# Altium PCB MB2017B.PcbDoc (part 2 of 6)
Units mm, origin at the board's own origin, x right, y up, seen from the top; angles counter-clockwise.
Board outline 148.19 x 169.19 mm, 4 copper layers (Top Layer, Mid Layer 1, Mid Layer 2, Bottom Layer), stack 1.498 mm thick; 458 components, 208 nets, 1223 pads, 6162 vias.
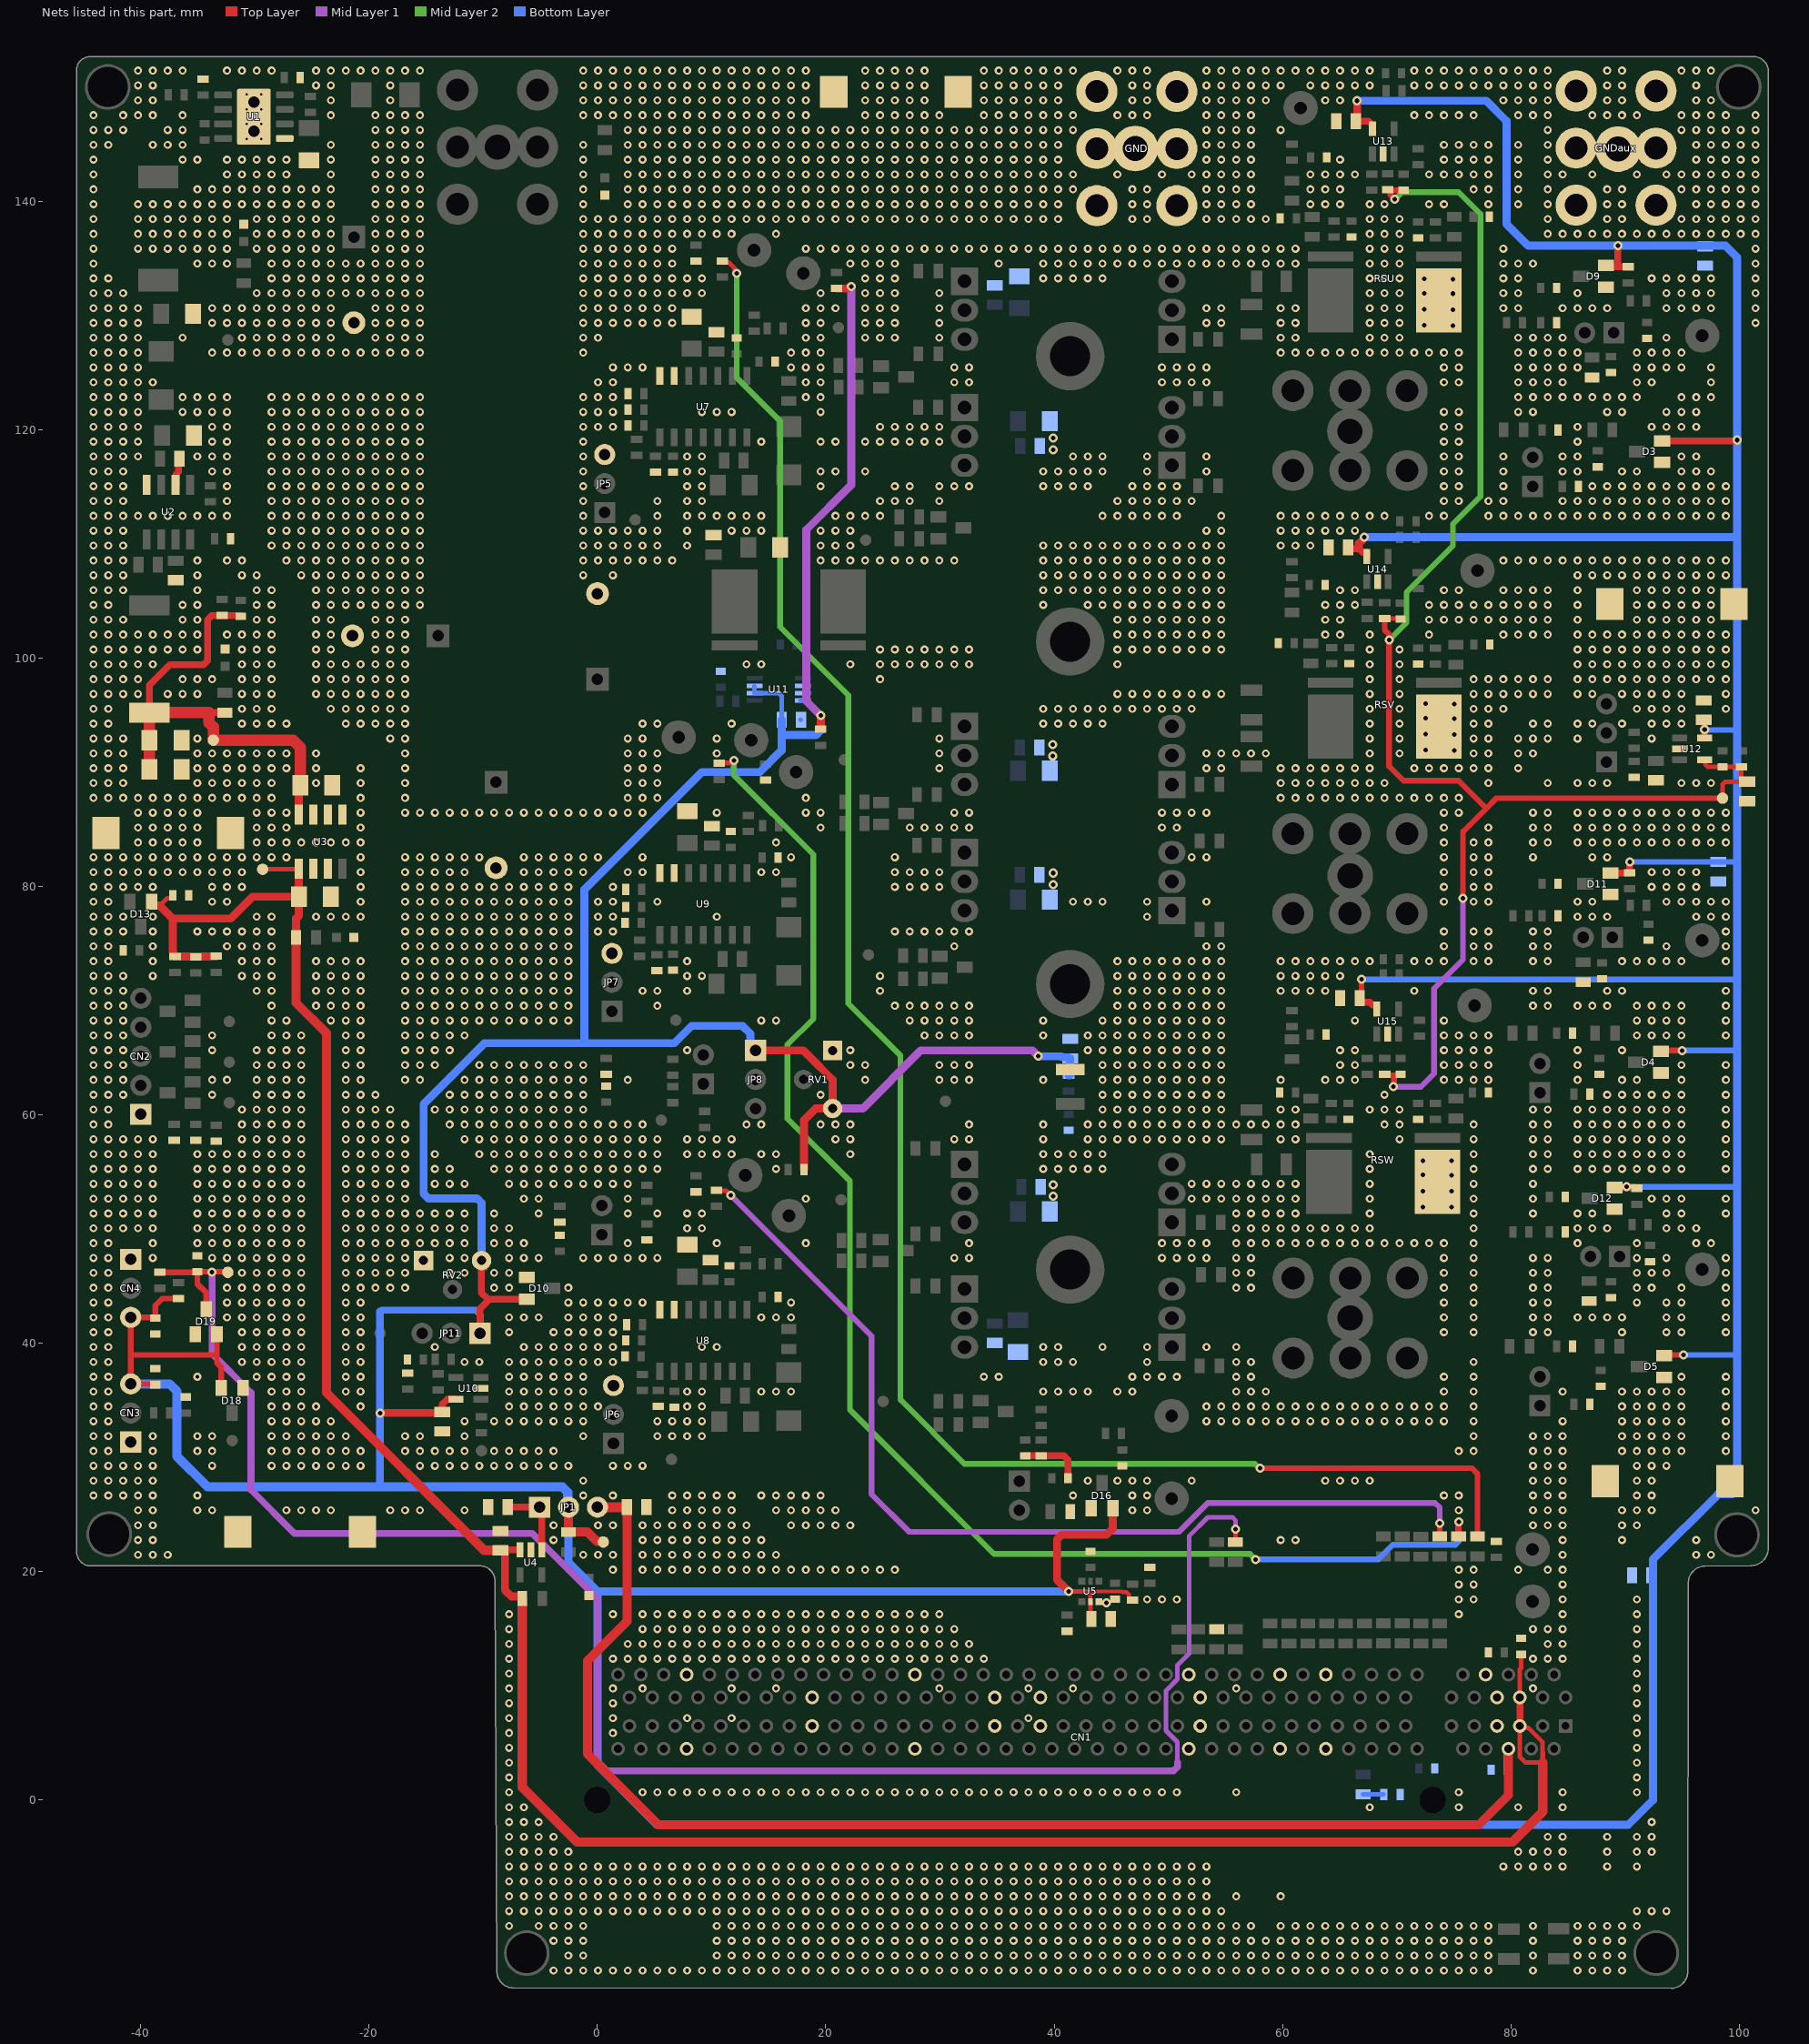
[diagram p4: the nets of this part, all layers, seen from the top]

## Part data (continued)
C21 C25 C26 C27 C28 C44 C45 C49 C64 C68 C69 C73 C79 C90 C93 C103 C107 C116 C119: library part MCD-01099, "Capacitor, MLCC, 100nF, 50V, X7R, +/-10%, 0603, T=0.8mm", Manufacturer=YAGEO, Manufacturer_Part_Number=CC0603KRX7R9BB104, Package=0603
C29 C30 C33 C37 C50 C52 C53: library part MCD-01093, "Capacitor, MLCC, 100nF, 100V, X7R, +/-10%, 0805, T=1.25mm", Manufacturer=TDK, Manufacturer_Part_Number=C2012X7R2A104K125AA, Package=0805
C36 C59 C70: library part MCD-00013, "Capacitor, MLCC, 4.7uF, 50V, X7R, +/-10%, 1206, T=1.27mm", Manufacturer=AVX, Manufacturer_Part_Number=12065C475KAT2A, Package=1206
C40 C46 C62: library part MCD-00609, "Capacitor, MLCC, 1uF, 50V, X7R, +/-10%, 1206, T=1.15mm", Manufacturer=MURATA, Manufacturer_Part_Number=GRM31MR71H105KA88L, Package=1206
C41 C43 C63 C67 C71 C72: library part MCD-01648, "Capacitor, MLCC, 100pF, 50V, NPO, +/-5%, 0603, T=0.8mm", Manufacturer=YAGEO, Manufacturer_Part_Number=CC0603JRNPO9BN101, Package=0603
C42 C47 C66: library part MCD-01102, "Capacitor, MLCC, 10nF, 50V ,X7R, +/-10%, 0603, T=0.8mm", Manufacturer=YAGEO, Manufacturer_Part_Number=CC0603KRX7R9BB103, Package=0603
C74 C81 C87 C99 C102 C117 C118: library part MCD-01101, "Capacitor, MLCC, 100pF, 50V, X7R, +/-5%, 0603, T=0.33mm", Manufacturer=AVX, Manufacturer_Part_Number=06035C101JAT4A, Package=0603
C75 C76 C83 C84 C88 C89: library part MCD-01052, "Capacitor, MLCC, 33nF, 50V, X7R, +/-5%, 0603, T=1.25mm", Manufacturer=AVX, Manufacturer_Part_Number=06035C333JAT2A, Package=0603
C80 C95 C96 C104 C105 C108 C109 C110 C112 C120 C121 C124 C125: library part MCD-01091, "Capacitor, MLCC, 1nF, 100V, X7R, +/-10%, 0603, T=0.8mm", Manufacturer=YAGEO, Manufacturer_Part_Number=CC0603KRX7R0BB102, Package=0603
C82 C85 C94 C100 C101: library part MCD-01098, "Capacitor, MLCC, 10nF, 100V, X7R, +/-10%, 0603, T=0.8mm", Manufacturer=YAGEO, Manufacturer_Part_Number=CC0603KRX7R0BB103, Package=0603
CN1: library part MCD-02664, "Socket_PCIE, 164 pins, RA, TH, T=9,45mm", Manufacturer=SAMTEC, Manufacturer_Part_Number=PCIE-164-02-S-D-RA
CN2: library part MCD-02060, "Header, 5x1, 2.54mm, VR, TH, T=5.84mm/2.54mm", Manufacturer=SAMTEC, Manufacturer_Part_Number=TSW-105-07-G-S
CN3 CN4: library part MCD-02272, "Header, 3x1, 2,54mm, VR, TH, T= 5.84mm/2.54mm", Manufacturer=SAMTEC, Manufacturer_Part_Number=TSW-103-07-F-S
D1 D2 D6 D7 D8: library part MCD-03397, "Diode, Ultrafast Recovery Rectifier, 0V89, 2A, 200V, DO-214AA", Manufacturer=STMICROELECTRONICS, Manufacturer_Part_Number=STTH2R02U, Package=DO-214AA
D3 D4 D5 D9 D10 D11 D12 D16 D18 D19: library part MCD-03277, "Diode, Schottky, 0V3, 300mA, 40V, SOT-23", Manufacturer=STMICROELECTRONICS, Manufacturer_Part_Number=BAT54SFILM, Package=SOT-23
D13 D14 D15 D17: library part MCD-03281, "Diode, Schottky, Single, 0V3, 300mA, 40V, SOT-23", Manufacturer=STMICROELECTRONICS, Manufacturer_Part_Number=BAT54FILM, Package=SOT-23
Enable HinU HinV HinW Icc_Current LinU LinV LinW Overcurrent ShuntU+ ShuntV+ ShuntW+ Vcc_power Vcc_PW VU VV VW: library part MCD-00713, "Black test terminal, Hole diameter=1.02mm", Manufacturer=VERO, Manufacturer_Part_Number=20-2137, Package=2.35x2.35mm
GND GNDaux VBAT VoutU VoutV VoutW: library part MCD-03715, "Connector, M4, SNAP IN, 1x1, VR, TH, T=11.68mm", Manufacturer="KEYSTONE ELECTRONICS", Manufacturer_Part_Number=7798, Package="M4 SNAP IN"
HW1: library part MISC_HEATSINK_Fischer_Elektronik_SK664100SA
J1 J2 J3 J4 J5 J6 Jdummy1 Jdummy2: library part MCD-03351, "Jumper, 1206, 50A, 200uR", Manufacturer=KOA, Manufacturer_Part_Number=TLRZ2BTTD, Package=1206
JP1 JP5 JP6 JP7 JP8 JP11 JP14: library part MCD-01905, "Header, 3x1, 2.54mm, VR, TH, T=5.84mm/2.54mm", Manufacturer=SAMTEC, Manufacturer_Part_Number=TSW-103-07-G-S
JP2 JP3 JP4 JP9 JP10 JP12 JP13 JP15 JP16: library part MCD-00045, "Header, 2x1, 2.54mm, VR, TH, T=5.84mm/2.54mm", Manufacturer=SAMTEC, Manufacturer_Part_Number=TSW-102-07-G-S
L1: library part MCD-03696, "Inductor, 68uH, +/-20%, 1.9A, 110mR, 10.5x10.3mm, T=5mm", Manufacturer="WURTH ELEKTRONIK", Manufacturer_Part_Number=7447714680, Package=10.5x10.3mm
L2: library part MCD-03623, "Inductor, 33uH, +/-20%, 2.3A, 93mR, SMT, T=3.8mm", Manufacturer=COILCRAFT, Manufacturer_Part_Number=MSS1038T-333MLC, Package=10x3.8x10.2mm
LD1: library part MCD-00589, "LED, Green, 3V2, 20mA, 0603", Manufacturer=VISHAY, Manufacturer_Part_Number=VLMTG1300-GS08, Package=0603
LD2 LD4: library part MCD-00587, "LED, Red, 2V, 20mA, 0603", Manufacturer=VISHAY, Manufacturer_Part_Number=VLMS1300-GS08, Package=0603
LD3: library part MCD-00591, "LED, Orange, 2V, 20mA, 0603", Manufacturer=VISHAY, Manufacturer_Part_Number=VLMO1300-GS08, Package=0603
LD5: library part MCD-00584, "LED, Blue, 3V3, 20mA, 0603", Manufacturer=VISHAY, Manufacturer_Part_Number=VLMB1300-GS08, Package=0603
MB2017B: library part MCD-03113
NTC1: library part MCD-03782, "NTC SMD Thermistor, 10k, 1206, +/-5%, 0.24W", Manufacturer=AVX, Manufacturer_Part_Number=NB20K00103JBA, Package=1206
Q1 Q10 Q11 Q12 Q13 Q18: library part MCD-03327, "Transistor, PNP, 20V, 1.5A, SOT-23", Manufacturer="DIODES INCORPORATED", Manufacturer_Part_Number=FMMT718TA, Package=SOT-23
Q2 Q3 Q4 Q5 Q6 Q7 Q8 Q9 Q14 Q15 Q16 Q17: library part MCD-03382, "Transistor, MOSFET, N-CH, 100V, 110A, TO-220", Manufacturer=STMICROELECTRONICS, Manufacturer_Part_Number=STP110N10F7, Package=TO-220
R1 R53 R54 R55 R56 R57 R58 R82 R103 R107: library part MCD-00070, "Resistor, 1K, 0603, +/-1%, 1/10W", Manufacturer=YAGEO, Manufacturer_Part_Number=RC0603FR-071KL, Package=0603
R2: library part MCD-00484, "Resistor, 470K, 0603, +/-1%, 1/10W", Manufacturer=YAGEO, Manufacturer_Part_Number=RC0603FR-07470KL, Package=0603
R3 R44: library part MCD-00223, "Resistor, 100K, 0603, +/- 1%, 1/10W", Manufacturer=YAGEO, Manufacturer_Part_Number=RC0603FR-07100KL, Package=0603
R4: library part MCD-03531, "Resistor, 1K5, 0805, +/-1%, 1/8W", Manufacturer=YAGEO, Manufacturer_Part_Number=RC0805FR-071K5L, Package=0805
R5: library part MCD-01171, "Resistor, 49K9, 0603, +/-1%, 1/10W", Manufacturer=YAGEO, Manufacturer_Part_Number=RC0603FR-0749K9L, Package=0603
R6: library part MCD-03530, "Resistor, 4K7, 0805, +/-1%, 1/8W", Manufacturer=YAGEO, Manufacturer_Part_Number=RC0805FR-074K7L, Package=0805
R7 R68 R72 R95 R99 R104 R105 R121 R138 R160 R178: library part MCD-00224, "Resistor, 100R, 0603, +/-1%, 1/10W", Manufacturer=YAGEO, Manufacturer_Part_Number=RC0603FR-07100RL, Package=0603
R8: library part MCD-01720, "Resistor, 499K, 0603, +/-1%, 1/10W", Manufacturer=YAGEO, Manufacturer_Part_Number=RC0603FR-07499KL, Package=0603
R9 R11 R13: library part MCD-03534, "Resistor, 470R, 0805, +/-1%, 1/8W", Manufacturer=YAGEO, Manufacturer_Part_Number=RC0805FR-07470RL, Package=0805
R10: library part MCD-00532, "Resistor, 82K, 0603, +/-1%, 1/10W", Manufacturer=YAGEO, Manufacturer_Part_Number=RC0603FR-0782KL, Package=0603
R12 R145 R159 R161 R163 R181 R182: library part MCD-01548, "Resistor, 10R, 0805, +/-1%, 1/8W", Manufacturer=YAGEO, Manufacturer_Part_Number=RC0805FR-0710RL, Package=0805
R14 R15 R124 R125 R146 R158 R162 R164 R173 R179 R180: library part MCD-00220, "Resistor, 10K, 0603, +/-1%, 1/10W", Manufacturer=YAGEO, Manufacturer_Part_Number=RC0603FR-0710KL, Package=0603
R16 R111: library part MCD-00430, "Resistor, 22K, 0603, +/-1%, 1/10W", Manufacturer=YAGEO, Manufacturer_Part_Number=RC0603FR-0722KL, Package=0603
R17 R184: library part MCD-00222, "Resistor, 47K, 0603, 1%, 1/10W", Manufacturer=YAGEO, Manufacturer_Part_Number=RC0603FR-0747KL, Package=0603
R18 R19 R20: library part MCD-01562, "Resistor, 6K8, 0805, +/-0.1%, 1/8W, +/-50ppm/°C", Manufacturer=YAGEO, Manufacturer_Part_Number=RT0805BRE076K8L, Package=0805
R21 R22 R23 R30 R31 R32 R33 R34 R35 R36 R37 R38 R39 R40 R41 R42 R43 R45 R46 R47 R48 R49 R50 R51 R52 R155 R170 R172 R183: library part MCD-00179, "Resistor, 0R, 0805, +/-5%, 1/8W", Manufacturer=YAGEO, Manufacturer_Part_Number=RC0805JR-070RL, Package=0805
R24 R25 R26 R27 R28 R29: library part MCD-03938, "Resistor, 2K, 0603, +/-1%, 1/10W", Manufacturer=YAGEO, Manufacturer_Part_Number=RC0603FR-072KL, Package=0603
R59 R60 R61 R78 R83 R84 R85 R86 R87 R88 R89 R90 R91 R108 R109: library part MCD-01111, "Resistor, 10R, 0805, +/-1%, 1/4W", Manufacturer=STACKPOLE, Manufacturer_Part_Number=RNCP0805FTD10R0, Package=0805
R62 R63 R65 R66 R70 R71 R75 R76 R92 R93 R97 R98: library part MCD-03477, "Resistor, 4R7, 0805, +/-1%, 1/8W", Manufacturer=YAGEO, Manufacturer_Part_Number=RC0805FR-074R7L, Package=0805
R64 R67 R69 R73 R94 R100: library part MCD-03667, "Resistor, 22K, 0805, +/-1%, 1/8W", Manufacturer=YAGEO, Manufacturer_Part_Number=RC0805FR-0722KL, Package=0805
R74 R96 R101: library part MCD-00510, "Resistor, 6K8, 0603, +/-1%, 1/10W", Manufacturer=YAGEO, Manufacturer_Part_Number=RC0603FR-076K8L, Package=0603
R77 R79 R102: library part MCD-00508, "Resistor, 680R, 0603, +/-1%, 1/10W", Manufacturer=YAGEO, Manufacturer_Part_Number=RC0603FR-07680RL, Package=0603
R80 R81 R106: library part MCD-03337, "Resistor, 3K6, 0603, +/-1%, 1/10W", Manufacturer=PANASONIC, Manufacturer_Part_Number=ERJ3EKF3601V, Package=0603
R110 R126: library part MCD-00384, "Resistor, 13K, 0603,+/-1%, 1/10W", Manufacturer=YAGEO, Manufacturer_Part_Number=RC0603FR-0713KL, Package=0603
R112: library part MCD-00197, "Resistor, 330R, 0603, +/-1%, 1/10W", Manufacturer=YAGEO, Manufacturer_Part_Number=RC0603FR-07330RL, Package=0603
R113: library part MCD-00450, "Resistor, 300R, 0603, +/-1%, 1/10W", Manufacturer=YAGEO, Manufacturer_Part_Number=RC0603FR-07300RL, Package=0603
R114 R122 R132: library part MCD-00347, "Resistor, 220K, 0603, +/-1%, 1/10W", Manufacturer=YAGEO, Manufacturer_Part_Number=RC0603FR-07220KL, Package=0603
R115 R123 R133: library part MCD-00522, "Resistor, 75K, 0603, +/-1%, 1/10W", Manufacturer=YAGEO, Manufacturer_Part_Number=RC0603FR-0775KL, Package=0603
R116 R127 R134 R144 R152 R154 R156 R165 R166 R169 R171 R174 R176: library part MCD-00186, "Resistor, 10R, 0603, +/-1%, 1/10W", Manufacturer=YAGEO, Manufacturer_Part_Number=RC0603FR-0710RL, Package=0603
R117 R130 R136 R150: library part MCD-00366, "Resistor, 11K, 0603, +/-1%, 1/10W", Manufacturer=YAGEO, Manufacturer_Part_Number=RC0603FR-0711KL, Package=0603
R118 R131 R137 R151: library part MCD-03670, "Resistor, 9K31, 0805, +/-1%, 1/8W", Manufacturer=YAGEO, Manufacturer_Part_Number=RC0805FR-079K31L, Package=0805
R119: library part MCD-02176, "Resistor, 2K8, 0603, +/-0.1%, 1/10W, +/-50ppm/°C", Manufacturer=YAGEO, Manufacturer_Part_Number=RT0603BRE072K8L, Package=0603
R120 R143: library part MCD-02183, "Resistor, 169K, 0603, +/-1%, 1/10W", Manufacturer=YAGEO, Manufacturer_Part_Number=RC0603FR-07169KL, Package=0603
R128: library part MCD-00428, "Resistor, 220R, 0603, +/-1%, 1/10W", Manufacturer=YAGEO, Manufacturer_Part_Number=RC0603FR-07220RL, Package=0603
R129: library part MCD-00056, "Resistor, 0R, 0603, +/-5%, 1/10W", Manufacturer=YAGEO, Manufacturer_Part_Number=RC0603JR-070RL, Package=0603
R135 R139: library part MCD-01566, "Resistor, 10K, 0603, +/-0.1%, 1/10W, +/-50ppm/°C", Manufacturer=YAGEO, Manufacturer_Part_Number=RT0603BRE0710KL, Package=0603
R140 R141 R142: library part MCD-00349, "Resistor, 2K2, 0603, +/-1%,1/10W", Manufacturer=YAGEO, Manufacturer_Part_Number=RC0603FR-072K2L, Package=0603
R147 R148 R149: library part MCD-01571, "Resistor, 4K22, 0603, +/-1%, 1/10W", Manufacturer=YAGEO, Manufacturer_Part_Number=RC0603FR-074K22L, Package=0603
R153 R157 R167 R168 R175 R177: library part MCD-00490, "Resistor, 560R, 0603, +/-1%, 1/10W", Manufacturer=YAGEO, Manufacturer_Part_Number=RC0603FR-07560RL, Package=0603
RPW RSU RSV RSW: library part MCD-03392, "Resistor, 0R001, 4026, 1%, 5W, Power Shunt Resistor with Senses, 129A", Manufacturer=VISHAY, Manufacturer_Part_Number=Y14780R00100F9R, Package=4026
RV1 RV2: library part MCD-02050, "Trimmer, 1k, 3386p, +/-10%, 1/2W, T=4.83mm", Manufacturer=BOURNS, Manufacturer_Part_Number=3386P-1-102TLF, Package=3386P
TP1 TP2 TP3 TP4 TP5: library part MCD-03485, "Test Point SMD H:1.8mm, L:10.16mm, l:1.8mm", Manufacturer=HARWIN, Manufacturer_Part_Number=S1621-46R
U1: library part MCD-03695, "Regulator, 1A, STEP DOWN SWITCHING, 6V To 100V, 1MHz", Manufacturer="TEXAS INSTRUMENTS", Package="SO8 EPAD"
U2: library part MCD-03622, "Regulator, 1.5A, SYNCHRONOUS STEP DOWN LNM SWITCHING CONVERTER , 3V5 to 38V, 400KHz", Manufacturer=STMICROELECTRONICS, Manufacturer_Part_Number=L6981NDR, Package=SO-8L
U3: library part MCD-03540, "DC Input voltage is from -0.5 V to 20V", Manufacturer=STMICROELECTRONICS, Manufacturer_Part_Number=KF50BD-TR, Package=SO-8
U4: library part MCD-02514, "LDO, 300mA, 28V, Low-dropout voltage, with 5uA quiescent current", Manufacturer=STMICROELECTRONICS, Package=SOT23-5
U5: library part MCD-04271, "DC switch, 9R, Low Voltage, 1:2 SPDT analog switch", Manufacturer="TEXAS INSTRUMENTS", Manufacturer_Part_Number=TS5A9411DCKR, Package=SC70-6
U7 U8 U9: library part MCD-03383, "Gate Driver, High Voltage, High and Low-side, 4A", Manufacturer=STMICROELECTRONICS, Manufacturer_Part_Number=L6491DTR, Package=SO-14
U10: library part MCD-02179, "Comparator, 1V8, Rail-to-rail, high-speed", Manufacturer=STMICROELECTRONICS, Manufacturer_HQ_COO=EU, Manufacturer_Part_Number=TS3021ILT, Package=SOT23-5
U11: library part MCD-04028, "Differential Current-Sense Amplifier, 650KHz Bandwidth, -4V To 100V, Gain 20V/V, 5V", Manufacturer=STMICROELECTRONICS, Package=MiniSO-8
U12: library part MCD-01192, "Operational Amplifier, Single/dual/quad rail-to-rail input/output, 5V5, 8MHz", Manufacturer=STMICROELECTRONICS, Manufacturer_HQ_COO=EU, Package=SOT23-5
U13 U14 U15: library part MCD-03445, "Single Op-amp, High bandwidth 50 MHz, low offset 200uV, rail-to-rail, 5V", Manufacturer=STMICROELECTRONICS, Package=SOT23-5

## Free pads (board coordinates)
  round 4 hole 3.5: 0(-42.903,150.049) 0(-42.776,23.303) 0(-6.2,-13.4) 0(92.75,-13.4) 0(99.822,23.241) 0(99.972,150.049)
  round 4 hole 2.2: 5(-8.763,144.78) 5(47.117,144.653) 5(65.913,119.888) 5(65.936,42.226) 5(65.936,80.961) 5(89.4,144.608)
  round 2 hole 1: 6(-30.099,146.177) 6(-30.099,148.717)

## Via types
v1: diameter 0.7, hole 0.35, Top Layer to Bottom Layer, tented both sides, 5935 vias
v2: diameter 0.8, hole 0.4, Top Layer to Bottom Layer, tented both sides, 216 vias
v3: diameter 1, hole 0.5, Top Layer to Bottom Layer, tented both sides, 9 vias
v4: diameter 0.8, hole 0.4, Top Layer to Bottom Layer, 2 vias

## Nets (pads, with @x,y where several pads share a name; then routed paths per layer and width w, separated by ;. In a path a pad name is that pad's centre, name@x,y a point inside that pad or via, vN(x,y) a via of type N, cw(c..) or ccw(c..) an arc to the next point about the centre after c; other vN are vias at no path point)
3V3_analog_power: 3V3.1 C17.2 C18.2 C77.2 C78.2 C86.2 C98.2 C103.1 C111.2 C113.2 C116.1 C126.2 C127.2 C128.2 CN3.3 CN4.3 D3.2 D4.2 D5.2 D9.2 D10.2 D11.2 D12.2 D16.2 D18.2 D19.2 JP1.2 JP8.1 JP11.1 R13.2 R14.2 R15.1 R54.2 R55.2 R57.1 R114.2 R122.2 R132.2 R173.2 RV1.3 RV2.3 U5.2 U10.5 U11.6 U11.7 U12.5 U13.5 U14.5 U15.5 | length 800.5
  Top Layer w0.35: U5.2@43.18,17.388 43.18,18.034 43.429,18.283 45.939,18.283 45.994,18.228 46.333,18.228 46.538,18.023 46.538,17.668 46.683,17.523 R14.2@46.863,17.523
  Top Layer w0.4: v2(41.275,18.288) 42.926,18.288 43.18,18.034 ; U5.2@43.18,17.388 43.18,15.953 C17.2@43.258,15.875
  Top Layer w0.5: C103.1@-38.735,36.384 -38.8,36.449 CN3.3@-40.894,36.449 -40.894,38.989 ; R173.2@-36.703,43.939 -38.103,43.939 -38.735,43.307 C116.1@-38.735,42.229 -38.797,42.291 CN4.3@-40.894,42.291 -40.894,38.989 ; D19.2@-33.34,40.81 -33.34,38.989 ; D18.2@-32.954,36.109 -32.954,37.907 -33.34,38.293 -33.34,38.989 ; C113.2@66.763,70.231 66.929,70.397 v2(66.929,71.882) ; D4.2@93.175,65.593 93.241,65.659 v2(94.996,65.659) ; D5.2@93.429,38.923 93.495,38.989 v2(95.123,38.989) ; -40.894,38.989 -33.34,38.989
  Top Layer w0.6: C77.2@-13.589,33.997 -13.589,34.671 -13.142,35.118 U10.5@-12.403,35.118 ; JP11.1@-10.287,40.894 -10.287,43.053 -9.591,43.749 -9.591,43.881 ; RV2.3@-9.903,46.654 -9.903,47.007 RV2.3@-10.16,47.264 -10.16,44.45 -9.591,43.881 ; D10.2@-6.18,43.881 -9.591,43.881 ; C111.2@65.747,109.728 65.874,109.601 66.698,109.601 67.026,109.273 67.376,109.273 U14.5@67.376,108.923 ; C98.2@66.421,147.066 67.556,147.066 67.884,146.738 U13.5@67.884,146.388 ; C113.2@66.763,70.231 66.763,70.055 66.913,69.905 67.659,69.905 67.915,69.649 68.265,69.649 U15.5@68.265,69.299 ; D9.2@88.349,134.427 88.472,134.304 89.384,134.304 ; D11.2@88.73,81.214 90.42,81.214 R122.2@90.424,81.218 v2(90.424,82.169) ; D12.2@89.111,53.655 90.818,53.655 90.879,53.594 R132.2@91.059,53.594 ; v2(89.408,136.144) 89.384,136.12 89.384,134.304 ; R114.2@90.297,134.304 89.384,134.304 ; D3.2@93.259,119.06 99.702,119.06 99.768,119.126 v2(99.822,119.126) ; C86.2@96.901,94.615 96.985,94.531 v2(96.985,93.778) U12.5@96.985,93.025
  Top Layer w0.7: v2(-19.05,33.909) -13.677,33.909 C77.2@-13.589,33.997 ; JP8.1@13.843,65.659 18.034,65.659 18.414,65.279 20.594,63.099 RV1.3@20.594,60.579 19.115,60.579 18.099,59.563 R57.1@18.099,55.245 ; R54.2@19.558,93.791 v2(19.558,94.996) ; R55.2@20.955,132.396 21.952,132.396 22.144,132.588 v2(22.225,132.588) ; v2(41.275,18.288) 40.259,19.304 40.259,22.831 40.669,23.241 44.577,23.241 45.146,23.81 D16.2@45.146,25.57 ; C98.2@66.421,147.066 66.521,147.166 66.521,147.616 66.548,147.643 v2(66.548,148.844) ; 66.698,109.601 66.698,110.057 67.183,110.542 v2(67.183,110.617)
  Top Layer w0.8: JP1.2@-2.54,25.654 R13.2@-2.54,23.481 -0.875,23.481 -0.038,22.644 0.47,22.644 3V3.1@0.508,22.606
  Mid Layer 1 w0.7: v2(19.558,94.996) 18.288,96.266 18.288,111.252 22.225,115.189 v2(22.225,132.588) ; RV1.3@20.594,60.579 23.241,60.579 28.321,65.659 38.1,65.659 v2(38.608,65.151)
  Bottom Layer w0.4: U11.7@13.75,97.607 U11.6@13.75,96.957 15.895,96.957 16.129,96.723 C78.2@16.129,94.615
  Bottom Layer w0.5: v2(66.929,71.882) 99.822,71.882 ; v2(90.17,53.721) 99.822,53.721 ; v2(90.424,82.169) C127.2@98.171,82.169 99.822,82.169 ; v2(94.996,65.659) 99.822,65.659 ; v2(95.123,38.989) 99.822,38.989 ; v2(96.985,93.778) 97.037,93.726 99.822,93.726
  Bottom Layer w0.6: -19.05,42.799 -18.915,42.934 -11.101,42.934 -11.093,42.926 -10.638,42.926 -10.287,42.575 JP11.1@-10.287,40.894
  Bottom Layer w0.7: -19.304,27.432 -19.05,27.686 v2(-19.05,33.909) -19.05,42.799 ; RV2.3@-10.16,47.264 -10.16,52.295 -10.57,52.705 -14.83,52.705 -15.24,53.115 -15.24,60.96 -9.906,66.294 -1.143,66.294 ; JP1.2@-2.54,25.654 -2.54,20.828 0,18.288 ; JP8.1@13.843,65.659 13.384,66.118 13.384,67.134 12.7,67.818 8.255,67.818 6.731,66.294 -1.143,66.294 ; C78.2@16.129,94.615 16.129,93.281 ; v2(19.558,94.996) 19.558,93.692 19.148,93.281 16.129,93.281 ; v2(38.608,65.151) 40.642,65.151 40.718,65.075 41.302,65.075 C18.2@41.402,64.975 41.402,63.53 41.372,63.5 R15.1@41.275,63.5 ; v2(41.275,18.288) 0,18.288 ; v2(66.548,148.844) 77.851,148.844 79.629,147.066 79.629,138.049 81.534,136.144 v2(89.408,136.144) 98.806,136.144 99.822,135.128 v2(99.822,119.126) 99.822,110.617 ; v2(67.183,110.617) 99.822,110.617 ; -1.143,66.294 -1.143,79.756 9.144,90.043 14.224,90.043 16.129,91.948 16.129,93.281 ; 0,18.288 0,3.048 5.207,-2.159 90.297,-2.159 92.456,0 92.456,21.082 98.171,26.797 99.412,26.797 99.822,27.207 99.822,38.989 99.822,53.721 99.822,65.659 99.822,71.882 99.822,82.169 99.822,93.726 99.822,110.617
  Bottom Layer w0.8: CN3.3@-40.894,36.449 -37.465,36.449 -36.83,35.814 -36.83,30.099 -34.163,27.432 -19.304,27.432 -3.076,27.432 -2.608,26.963 -2.608,25.722 JP1.2@-2.54,25.654
3V3_pci: C16.2 C26.1 CN1.A06 JP1.3 | length 115.9
  Top Layer w0.8: C16.2@2.579,25.654 2.579,15.66 -0.889,12.192 -0.889,4.064 5.334,-2.159 77.216,-2.159 79.8,0.425 CN1.A06@79.8,4.5
  Top Layer w0.9: JP1.3@0,25.654 C16.2@2.579,25.654
  Bottom Layer w0.7: C26.1@79.694,2.667 CN1.A06@79.694,4.286
  Bottom Layer w0.8: CN1.A06@79.694,4.286 79.8,4.392 CN1.A06@79.8,4.5
3V3_power: C15.2 JP1.1 U4.1 | length 6.6
  Top Layer w0.6: C15.2@-7.874,25.654 JP1.1@-5.08,25.654 -4.892,25.466 U4.1@-4.892,21.928
+5V_power: 5V.1 C13.2 C14.2 C25.1 C90.1 CN1.A05 CN1.B05 D13.1 R11.2 R12.1 R140.2 R141.2 R142.2 U3.1 U4.3 | length 230.2
  Top Layer w0.4: -38.342,78.347 -37.686,79.003 -37.331,79.003 -37.211,79.123 C90.1@-37.211,79.248 ; 5V.1@-29.337,81.534 -26.2,81.534 U3.1@-26.162,81.572 ; CN1.B05@80.8,9 80.8,11.458 80.899,11.557 C25.1@80.899,12.762 ; 80.8,3.782 CN1.A05@80.8,6.5 80.953,6.347 81.537,6.347 82.8,5.084 82.8,4.191 82.804,4.187 82.804,3.302 81.28,3.302 80.8,3.782
  Top Layer w0.6: C14.2@-8.679,21.733 -8.529,21.883 C14.2@-8.509,21.883 ; C14.2@-8.105,21.928 U4.3@-6.792,21.928 ; R12.1@-6.715,17.839 -6.59,17.714 R12.1@-6.59,17.653 ; CN1.A05@80.8,6.5 CN1.B05@80.8,9
  Top Layer w0.7: D13.1@-39.055,78.697 -39.055,78.497 -38.905,78.347 -38.342,78.347 -37.211,77.216 ; R142.2@-33.401,73.914 -33.416,73.899 R140.2@-37.005,73.899 -37.125,73.899 -37.155,73.929 -37.155,74.253 -37.211,74.309 -37.211,77.216 ; R11.2@-26.402,75.565 -26.402,77.23 -26.162,77.47 C13.2@-26.162,79.121 ; U3.1@-26.162,81.572 C13.2@-26.162,79.121 ; C14.2@-8.105,21.928 -8.105,18.392 -7.552,17.839 R12.1@-6.715,17.839 ; -37.211,77.216 -32.131,77.216 -30.226,79.121 C13.2@-26.162,79.121
  Top Layer w0.8: R11.2@-26.402,75.565 -26.402,69.836 -23.749,67.183 -23.749,35.687 -9.945,21.883 C14.2@-8.529,21.883 ; R12.1@-6.59,17.653 -6.59,1.129 -1.778,-3.683 80.137,-3.683 82.804,-1.016 82.804,3.302
+6V: 6V.1 C8.2 C9.2 C11.2 C12.2 L2.2 R8.2 R9.2 U3.8 | length 43
  Top Layer w0.6: L2.2@-39.243,95.249 -39.243,97.663 -37.465,99.441 -34.514,99.441 -34.163,99.792 -34.163,103.408 -33.812,103.759 R8.2@-32.893,103.759 C11.2@-31.242,103.759 ; -34.036,95.249 -34.035,95.25 R9.2@-32.639,95.25
  Top Layer w0.7: U3.8@-26.162,86.322 -26.162,88.773 C12.2@-26.035,88.9
  Top Layer w1: C8.2@-39.243,90.297 C9.2@-39.243,92.837 L2.2@-39.243,95.249 -34.036,95.249 -34.036,94.361 -33.655,93.98 6V.1@-33.655,92.837 -26.67,92.837 -26.035,92.202 C12.2@-26.035,88.9
BEMF_Ctrl: R49.1
Bias: Bias.1 C92.2 C94.2 C97.2 C114.2 C115.2 R138.2 R146.2 R162.2 R164.2 U12.4 | length 137.3
  Top Layer w0.4: R162.2@68.961,103.502 70.296,103.502 C114.2@70.358,103.44 ; U12.4@96.985,91.125 97.028,91.082 97.028,90.72 97.262,90.486 C94.2@98.552,90.486 R138.2@100.203,90.486 100.203,89.711 100.211,89.703 100.211,89.453 100.461,89.203 98.786,89.203 98.552,88.969 Bias.1@98.552,87.757
  Top Layer w0.5: R164.2@68.961,63.562 69.031,63.492 69.659,63.492 ; R162.2@68.961,103.502 68.961,102.489 69.342,102.108 v2(69.342,101.6) 69.342,90.551 70.612,89.281 75.438,89.281 77.851,86.868 ; v2(69.723,62.484) 69.776,62.537 69.776,63.376 69.659,63.492 ; v2(69.85,140.208) 69.465,140.593 69.465,140.997 69.457,141.005 69.277,141.005 C97.2@70.612,141.005 ; C115.2@70.358,63.562 70.288,63.492 69.659,63.492 ; v2(75.819,78.994) 75.819,84.836 77.851,86.868 ; Bias.1@98.552,87.757 78.74,87.757 77.851,86.868
  Mid Layer 1 w0.5: v2(69.723,62.484) 72.136,62.484 73.279,63.627 73.279,71.081 75.819,73.621 v2(75.819,78.994)
  Mid Layer 2 w0.5: v2(69.342,101.6) 70.866,103.124 70.866,105.791 74.93,109.855 74.93,111.76 77.343,114.173 77.343,138.938 75.438,140.843 70.485,140.843 v2(69.85,140.208)
Brake_Levers: Brake_Levers.1 C119.1 D19.3 R50.2 R178.2 | length 158.1
  Top Layer w0.4: R50.2@55.88,22.592 v2(55.88,23.749)
  Top Layer w0.5: R178.2@-38.354,46.231 -35.111,46.231 C119.1@-35.052,46.29 ; D19.3@-34.29,43.01 -34.29,44.45 -35.052,45.212 C119.1@-35.052,46.29 ; Brake_Levers.1@-32.385,46.228 -32.447,46.29 C119.1@-35.052,46.29
  Mid Layer 1 w0.4: 50.8,3.302 50.8,5.086 49.8,6.086 49.8,9.586 50.8,10.586 50.8,11.811 51.816,12.827 51.816,23.114 53.467,24.765 55.626,24.765 55.88,24.511 v2(55.88,23.749)
  Mid Layer 1 w0.6: v2(-33.769,46.229) -33.769,39.103 -30.353,35.687 -30.353,27.178 -26.543,23.368 -5.715,23.368 0,17.653 0,3.399 0.821,2.578 50.449,2.578 50.8,2.929 50.8,3.302
En1: R36.2 R82.1 | length 165.2
  Top Layer w0.4: R82.1@10.922,134.812 11.042,134.692 11.485,134.692 11.683,134.494 12.012,134.165 12.012,134.019 12.192,133.839 v2(12.192,133.731)
  Top Layer w0.5: v2(58.039,29.083) 76.581,29.083 77.089,28.575 R36.2@77.089,23.1
  Mid Layer 2 w0.5: v2(12.192,133.731) 12.192,124.587 16.002,120.777 16.002,102.743 21.971,96.774 21.971,69.775 26.54,65.206 26.54,35.055 32.131,29.464 57.577,29.464 57.958,29.083 v2(58.039,29.083)
En2: R39.2 R107.1 | length 126.8
  Top Layer w0.4: R107.1@10.668,90.808 10.701,90.841 11.612,90.841 11.83,91.059 v2(11.938,91.059)
  Top Layer w0.5: R39.2@75.438,23.1 v2(75.438,24.384)
  Mid Layer 2 w0.5: v2(11.938,91.059) 11.938,89.789 18.897,82.83 18.897,68.427 16.637,66.167 16.637,59.69 22.11,54.217 22.11,34.2 34.734,21.576 57.164,21.576 v2(57.658,21.082)
  Bottom Layer w0.5: v2(57.658,21.082) 68.394,21.082 69.664,22.352 75.145,22.352 75.438,22.645 v2(75.438,24.384)
En3: R42.2 R103.1 | length 87.6
  Top Layer w0.4: R103.1@10.414,53.405 10.447,53.372 11.25,53.372 11.663,52.959 v2(11.684,52.959)
  Top Layer w0.5: R42.2@73.787,23.1 v2(73.787,24.257)
  Mid Layer 1 w0.5: v2(11.684,52.959) 24.003,40.64 24.003,26.797 27.305,23.495 50.927,23.495 53.467,26.035 73.367,26.035 73.787,25.615 v2(73.787,24.257)
Epad: pad.6 U1.9
ETR: R183.2 R184.2 | length 1.8
  Bottom Layer w0.4: R183.2@67.056,0.508 R184.2@68.896,0.508
GND: C2.2 C3.1 C4.1 C5.1 C6.1 C8.1 C9.1 C10.1 C12.1 C13.1 C14.1 C15.1 C16.1 C17.1 C18.1 C19.1 C20.1 C21.1 C22.1 C23.1 C24.1 C25.2 C26.2 C27.2 C28.2 C29.2 C30.2 C31.2 C32.2 C33.2 C34.2 C35.2 C36.1 C37.2 C38.1 C41.1 C42.2 C43.1 C44.1 C45.1 C47.2 C49.1 C50.2 C51.2 C52.2 C53.2 C54.2 C55.2 C56.2 C57.2 C58.2 C59.1 C60.1 C63.1 C64.1 C65.1 C66.2 C67.1 C68.1 C69.1 C70.1 C71.1 C72.1 C73.1 C74.1 C75.1 C76.1 C77.1 C78.1 C79.2 C80.1 C81.1 C83.1 C84.1 C85.1 C86.1 C87.1 C88.1 C89.1 C90.2 C91.1 C92.1 C93.2 C95.2 C96.2 C98.1 C99.1 C100.1 C101.1 C102.1 C103.2 C104.2 C105.1 C107.2 C108.2 C109.2 C110.2 C111.1 C112.2 C113.1 C116.2 C117.1 C118.1 C119.2 C120.1 C121.1 C124.1 C125.1 C126.1 C127.1 C128.1 CN1.A07 CN1.A20 CN1.A24 CN1.A31 CN1.A32 CN1.A45 CN1.A49 CN1.A56 CN1.A65 CN1.A76 CN1.B07 CN1.B08 CN1.B20 CN1.B24 CN1.B31 CN1.B32 CN1.B45 CN1.B49 CN1.B56 CN1.B65 CN1.B76 CN2.1 CN3.1 CN4.1 D3.1 D4.1 D5.1 D9.1 D10.1 D11.1 D12.1 D16.1 D18.1 D19.1 GND.1 GNDaux.1 JP5.3 JP6.3 JP7.3 LD1.2 LD2.2 LD3.2 LD4.2 LD5.2 NTC1.1 pad.5@47.117,144.653 pad.5@89.4,144.608 R3.1 R5.1 R10.1 R16.1 R17.1 R24.1 R25.1 R26.1 R27.1 R28.1 R29.1 R44.1 R53.2 R56.1 R58.1 R74.1 R80.1 R81.1 R96.2 R101.1 R106.1 R113.1 R117.1 R118.1 R124.1 R125.1 R129.1 R130.1 R131.1 R136.1 R137.1 R139.1 R147.1 R148.1 R149.1 R150.1 R151.1 R184.1 RSU.F1 RSV.F1 RSW.F1 RV1.1 RV2.1 TP1.1 TP1.2 TP2.1 TP2.2 TP3.1 TP3.2 TP4.1 TP4.2 TP5.1 TP5.2 U1.1 U2.6 U2.8 U3.2 U3.3 U3.5 U3.6 U3.7 U4.2 U5.3 U7.6 U7.7 U8.6 U8.7 U9.6 U9.7 U10.2 U11.2 U11.3 U11.4 U12.2 U13.2 U14.2 U15.2 | length 8.4
  Top Layer w0.5: v2(44.577,17.272) v2@44.658,17.272 ; C21.1@45.269,17.518 C21.1@45.339,17.588
  Top Layer w0.6: U2.6@-36.957,115.189 -36.907,115.239 -36.907,116.128 -36.703,116.332 -36.703,117.387 C5.1@-36.615,117.475 ; C100.1@37.465,30.161 R150.1@38.862,30.161 40.862,30.161 41.213,29.81 C101.1@41.213,28.194
  Bottom Layer w0.4: C78.1@17.78,94.664 C78.1@17.829,94.615 ; U11.4@17.78,96.307 U11.4@18,96.307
